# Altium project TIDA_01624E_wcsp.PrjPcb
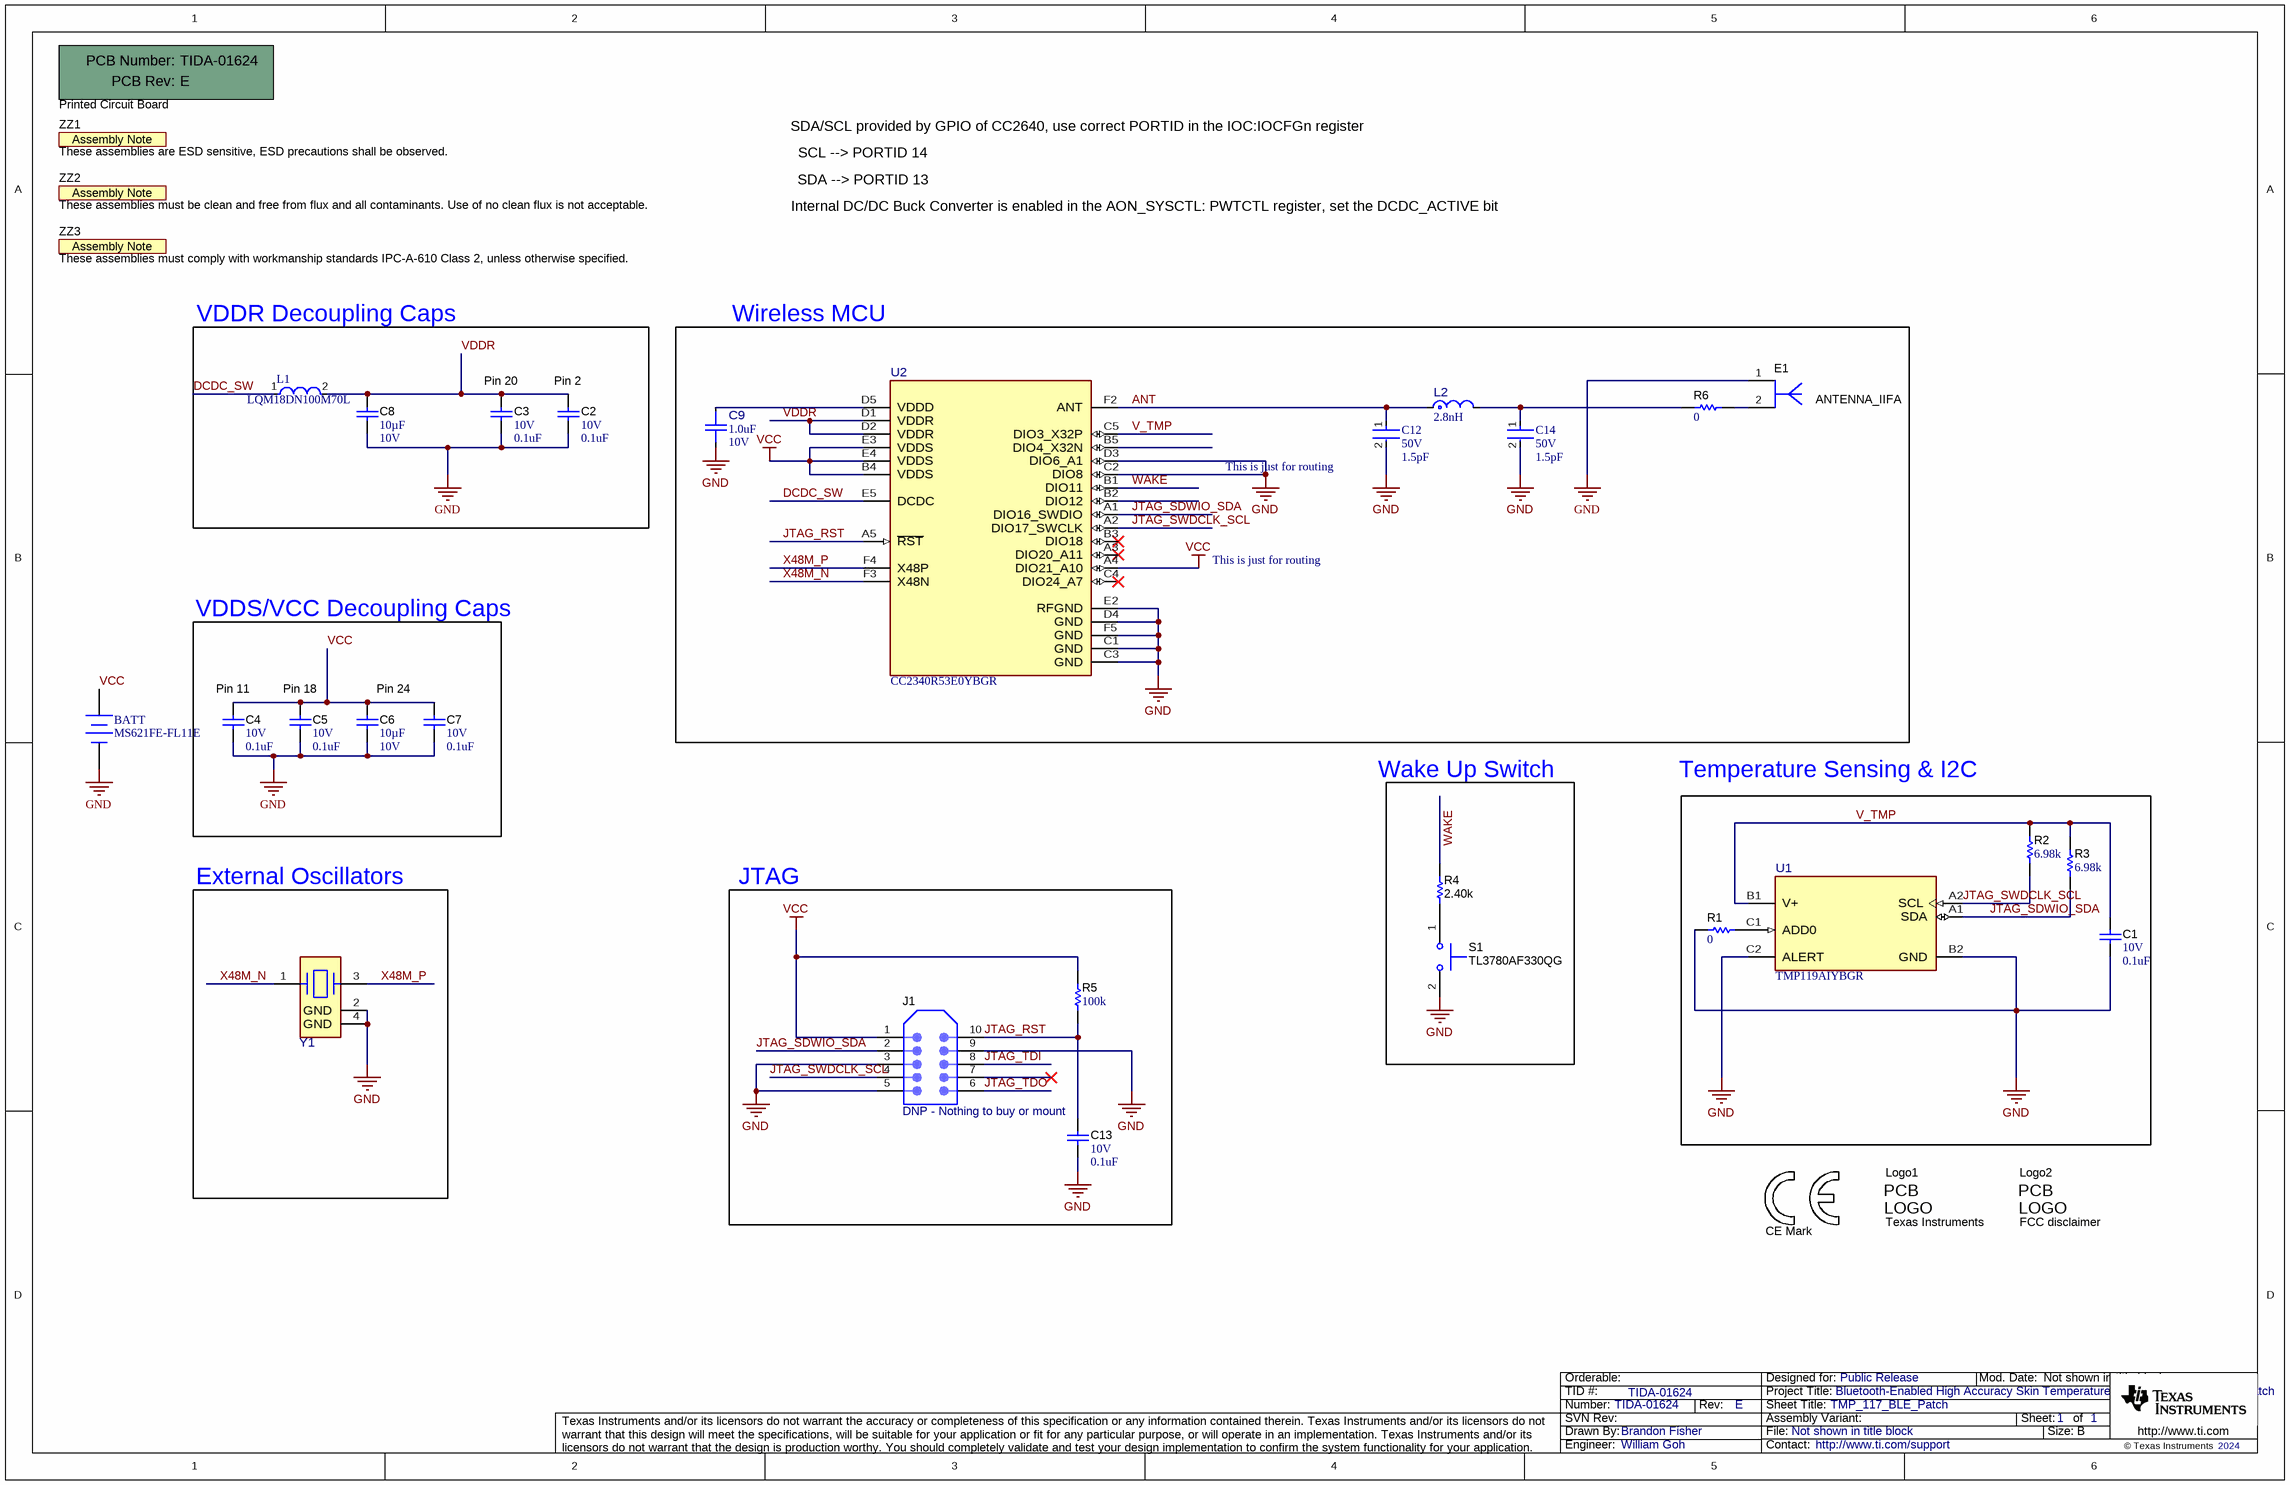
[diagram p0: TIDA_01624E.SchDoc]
TID: TIDA-01624; TechSupport: http://www.ti.com/support; SCH_Rev: E; PRJ_Title: Bluetooth-Enabled High Accuracy Skin Temperature Measurement Flex PCB Patch; PRJ_Number: TIDA-01624; PRJ_Engineer: William Goh; PRJ_Customer: Public Release; PCB_Rev: E; PCB_Layout: William Goh; CopyrightYear: 2024
1 sheet, 34 parts. Net scope: global (net labels, ports and power ports of the same name join across sheets).
Board file: TIDA_01624E.PcbDoc

## Sheet TIDA_01624E.SchDoc: TMP_117_BLE_Patch
size 431 x 279 mm; Date: Not shown in title block; ApprovedBy: Not shown in title block; CheckedBy: Not shown in title block; Author: Not shown in title block; CompanyName: Not shown in title block; DrawnBy: Brandon Fisher; Engineer: Not shown in title block; Organization: Not shown in title block; Address1: Not shown in title block; Address2: Not shown in title block; Address3: Not shown in title block; Address4: Not shown in title block; DocumentNumber: 1; Revision: Use project parameter SCH_Rev; SheetNumber: 1; SheetTotal: 1; PageSetup: Record=PageOptions¦CenterHorizontal=True¦CenterVertical=True¦PrintScale=1.00¦XCorrection=1.00¦YCorrection=1.00¦PrintKind=0¦BorderSize=5000000¦LeftOffset=0¦BottomOffset=0¦Orientation=2¦PaperLength=1000¦PaperWidth=1000¦Scale=100¦PaperSource=15¦PrintQuality=600¦MediaType=1¦DitherType=10¦PaperKind=Letter¦PrintScaleMode=1

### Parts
!PCB1  Printed Circuit Board  (mechanical)
BATT  MS621FE-FL11E  [SEIK-MS621FE-FL11E-2_V]
C1  VDC_V: 10V  ValueDisplayed: 0.1uF  [0201]  (hidden comment: GRM033C71A104KE14D)
C2  VDC_V: 10V  ValueDisplayed: 0.1uF  [0201]  (hidden comment: GRM033C71A104KE14D)
C3  VDC_V: 10V  ValueDisplayed: 0.1uF  [0201]  (hidden comment: GRM033C71A104KE14D)
C4  VDC_V: 10V  ValueDisplayed: 0.1uF  [0201]  (hidden comment: GRM033C71A104KE14D)
C5  VDC_V: 10V  ValueDisplayed: 0.1uF  [0201]  (hidden comment: GRM033C71A104KE14D)
C6  Cap_F: 10µF  VDC_V: 10V  [0603]  (hidden comment: GRM188Z71A106KA73D)
C7  VDC_V: 10V  ValueDisplayed: 0.1uF  [0201]  (hidden comment: GRM033C71A104KE14D)
C8  Cap_F: 10µF  VDC_V: 10V  [0603]  (hidden comment: GRM188Z71A106KA73D)
C9  ValueDisplayed: 1.0uF  VDC_V: 10V  [FP-GRM155Z71A105KE01D_0402-MFG]  (hidden comment: GRM155Z71A105KE01D)
C12  Voltage Rating: 50V  Capacitance: 1.5pF  [FP-GRM033-0_03-IPC_C]  (hidden comment: GRM0335C1H1R5BA01J)
C13  VDC_V: 10V  ValueDisplayed: 0.1uF  [0201]  (hidden comment: GRM033C71A104KE14D)
C14  Voltage Rating: 50V  Capacitance: 1.5pF  [FP-GRM033-0_03-IPC_C]  (hidden comment: GRM0335C1H1R5BA01J)
E1  ANTENNA_IIFA  [ANTENNA_IIFA]  (net tie)
J1  DNP - Nothing to buy or mount  [Tag_TC2050-NL]  (no BOM)
L1  LQM18DN100M70L  [FP-LQM18DN_70-IPC_B]
L2  value 2.8nH  [FP-LQP03TN2N8B02J_0201 (0603)-MFG]  (hidden comment: LQP03TN2N8B02J)
Logo1  Texas Instruments  [TI_Symbol_Overlay_Small]  (no BOM)
Logo2  FCC disclaimer  [FCC_disclaimer]  (no BOM)
Logo4  CE Mark  [CE_Mark_5mm]  (no BOM)
R1  ValueDisplayed: 0  [0402L]  (hidden comment: RC0402JR-070RL)
R2  ValueDisplayed: 6.98k  [0201]  (hidden comment: RC0201FR-7D6K98L)
R3  ValueDisplayed: 6.98k  [0201]  (hidden comment: RC0201FR-7D6K98L)
R4  ValueDisplayed: 2.40k  [0402]  (hidden comment: ERJ-2RKF2401X)
R5  ValueDisplayed: 100k  [0201]  (hidden comment: RC0201JR-7D100KL)
R6  ValueDisplayed: 0  [0201]  (hidden comment: CRCW02010000Z0ED)
S1  TL3780AF330QG  [SW_TL3780]
U1  TMP119AIYBGR  [YBG0006-C01-MFG]
U2  CC2340R53E0YBGR  [YBG0028-C01-MFG]
Y1  TZ3908AAAO43  [FP-TZ3908AAAO43_SMT4_2MM05_1MM65-MFG]  (value not drawn)
ZZ1  These assemblies are ESD sensitive, ESD precautions shall be observed.  [AssemblyNote]  (no BOM)
ZZ2  These assemblies must be clean and free from flux and all contaminants. Use of no clean flux is not acceptable.  [AssemblyNote]  (no BOM)
ZZ3  These assemblies must comply with workmanship standards IPC-A-610 Class 2, unless otherwise specified.  [AssemblyNote]  (no BOM)

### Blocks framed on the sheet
VDDR Decoupling Caps: C2 C3 C8 L1
Wireless MCU: C9 C12 C14 E1 L2 R6 U2
VDDS/VCC Decoupling Caps: C4-C7
Wake Up Switch: R4 S1
External Oscillators: Y1
JTAG: C13 J1 R5

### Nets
GND: BATT.2(-) C1.1 C2.1 C3.1 C4.1 C5.1 C6.1 C7.1 C8.1 C9.2 C12.2 C13.1 C14.2 E1.1 J1.3 J1.5 J1.9 R1.2 S1.2 U1.B2(GND) U1.C2(ALERT) U2.C1(GND) U2.C2(DIO8) U2.C3(GND) U2.D3(DIO6_A1) U2.D4(GND) U2.E2(RFGND) U2.F5(GND) Y1.2(GND) Y1.4(GND)
VCC: BATT.1(+) C4.2 C5.2 C6.2 C7.2 J1.1 R5.1 U2.A4(DIO21_A10) U2.B4(VDDS) U2.E3(VDDS) U2.E4(VDDS)
ANT: C12.1 L2.1 U2.F2(ANT)
DCDC_SW: L1.1 U2.E5(DCDC)
JTAG_RST: C13.2 J1.10 R5.2 U2.A5(~{RST})
JTAG_SDWIO_SDA: J1.2 R3.2 U1.A1(SDA) U2.A1(DIO16_SWDIO)
JTAG_SWDCLK_SCL: J1.4 R2.2 U1.A2(SCL) U2.A2(DIO17_SWCLK)
JTAG_TDI: J1.8
JTAG_TDO: J1.6
V_TMP: C1.2 R2.1 R3.1 U1.B1(V+) U2.C5(DIO3_X32P)
VDDR: C2.2 C3.2 C8.2 L1.2 U2.D1(VDDR) U2.D2(VDDR)
WAKE: R4.1 U2.B1(DIO11)
X48M_N: U2.F3(X48N) Y1.1(1_IN/OUT)
X48M_P: U2.F4(X48P) Y1.3(2_IN/OUT)
NetC9_1: C9.1 U2.D5(VDDD)
NetC14_1: C14.1 L2.2 R6.1
NetE1_2: E1.2 R6.2
NetR1_1: R1.1 U1.C1(ADD0)
NetR4_2: R4.2 S1.1

Not connected (* = marked no-connect by the designer): J1 7*; U2 A3(DIO20_A11)* B2(DIO12) B3(DIO18)* B5(DIO4_X32N) C4(DIO24_A7)*

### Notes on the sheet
- SCL --> PORTID 14
- SDA/SCL provided by GPIO of CC2640, use correct PORTID in the IOC:IOCFGn register
- SDA --> PORTID 13
- Internal DC/DC Buck Converter is enabled in the AON_SYSCTL: PWTCTL register, set the DCDC_ACTIVE bit
- (near C3) Pin 20
- (near C2) Pin 2
- (near C12) This is just for routing
- This is just for routing
- (near C4) Pin 11
- (near C5) Pin 18
- Pin 24
- Temperature Sensing & I2C

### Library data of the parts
!PCB1 = CMP-0003618-2: Manufacturer: Any; PartNumber: TIDA-01624
BATT = CMP-2000-05342-1: MS Lihium Rechargeable Battery, 3 V, -20 to 60 degC, Tray; Manufacturer: SeikoInstruments; Brand: SeikoInstrumentsMicroEnergy; Output Voltage: 3V; Capacity: 5.5mAh; Chemistry: Lithium; Battery Size: 621; Unit Weight: 0.008113oz
C1-C5 C7 C13 = CMP-0064969-1: CAP, CERM, 0.1 uF, 10 V,+/- 10%, X7S, 0201; Manufacturer: MuRata; TaMin_C: -55°C; Polarized: N; SizeAreaWB_mm2: 2.08; Value1: Unknown; U/M: EA; Value: 0.1uF; TaMax_C: 125°C; SizeZ_mm: 0.26; SizeX_mm: 0.6; SizeY_mm: 0.3; SizeArea_mm2: 0.18; Cap_F: 100nF; AEC Category: Q200
C6 C8 = CMP-0087107-2: Chip Multilayer Ceramic Capacitors for General Purpose; Manufacturer: Murata; TempCo: 15%; AEC Qualified: No; SizeZ_mm: 1mm; Tolerance_%: 10%
C9 = CMP-0092999-1: Chip Multilayer Ceramic Capacitors for General Purpose, 0402, 1.0uF, X7R, 15%, 10%, 10V; Manufacturer: Murata; Cap_F: 1µF; AEC Qualified: No; SizeZ_mm: 0.6mm; Value: 1µF
C12 C14 = CMP-06035-002174-1: Chip Multilayer Ceramic Capacitors for General Purpose, 0201, 1.5pF, C0G, 30ppm/°C, 0.1pF, 50V
E1 = CMP-0001736-1: PCB Antenna.  There is nothing to buy or mount.
J1 = CMP-0075101-1: Footprint for Tag-Connect TC2050 No-Legs cables; PartNumber: TC2050-IDC-NL-FP; Note: Footprint only, to mate with Tag-Connect TC2050 No-Legs cables; CT: False; CompType: Receptacle
L1 = CMP-06042-017052-1: Multilayer type Inductor for Power Lines 10uH ±20% @1MHz, 300mA, Max DCR 1.365Ω, SRF 32MHz
L2 = CMP-0001349-1: Film type RF Inductor 2.8nH ±0.1nH 500mA 0.2Ω 0201 (0603); Manufacturer: Murata; AEC Qualified: No; DCR_ohm: 0.2; SizeZ_mm: 0.33mm; Q Factor: 14; Self Resonant Frequency: 9.5GHz; Test Frequency: 500MHz
Logo1 = CMP-0074838-1: Texas Instrument Corporate Signature; SymbolCreator: a0412235; Lib Reference: TI_Logo
Logo2 = CMP-0074847-1: FCC_disclaimer
Logo4 = CMP-0074844-1: SymbolCreator: a0412235
R1 = CMP-0027004-2: RES, 0, 5%, 0.063 W, 0402; Manufacturer: Yageo America; Power_W: 63mW; TempCo: 200 ppm/C; Value_Code: 0000; U/M: EA; Value: 0; EIA_Code: E24; SizeX_mm: 1; SizeY_mm: 0.5; SizeZ_mm: 0.6; Value2: 0.063W; VDC_V: 50V; AEC Category: Q200
R2 R3 = CMP-0028058-1: RES, 6.98 k, 1%, 0.05 W, 0201; Manufacturer: Yageo America; Power_W: 50mW; TempCo: 200 ppm/C; Value_Code: 6k98; U/M: EA; Value: 6.98k; EIA_Code: E96; SizeX_mm: 0.6; SizeY_mm: 0.3; SizeZ_mm: 0.26; Value2: 0.05W; SizeArea_mm2: 0.18; AEC Qualified: N; VDC_V: 25V; AEC Category: Q200
R4 = CMP-0026685-1: RES, 2.40 k, 1%, 0.1 W, AEC-Q200 Grade 0, 0402; Manufacturer: Panasonic; Power_W: 100mW; TempCo: 100 ppm/C; Value_Code: 2k40; U/M: EA; Value: 2.40k; Res_ohm: 2.4k; SizeX_mm: 1; SizeY_mm: 0.5; SizeZ_mm: 0.6; Value2: 0.1W; CompType: Resistor; AEC Qualified: Y; AEC Grade: 0; AEC Category: Q200
R5 = CMP-0027184-1: RES, 100 k, 5%, 0.05 W, 0201; Manufacturer: Yageo America; Power_W: 50mW; TempCo: 200 ppm/C; U/M: EA; Value: 100k; EIA_Code: E24; SizeX_mm: 0.6; SizeY_mm: 0.3; SizeZ_mm: 0.26; Value2: 0.05W; SizeArea_mm2: 0.18; AEC Qualified: N; VDC_V: 25V; AEC Category: Q200
R6 = CMP-0027008-4: RES, 0, 5%, 0.05 W, 0201; Manufacturer: Vishay-Dale; Power_W: 50mW; TempCo: ppm/C; Value_Code: 0000; Value: 0; EIA_Code: E24; SizeX_mm: 0.6; SizeY_mm: 0.3; SizeZ_mm: 0.26; Value2: 0.05W; SizeArea_mm2: 0.18; AEC Qualified: N; AEC Category: Q200
S1 = CMP-0084104-1: Switch, SPST-NO, 0.05 A, 12 VDC, SMT; Manufacturer: E-Switch; CurrentRating_mA: 50A; SizeAreaWB_mm2: 13.5; PositionCount: 1; SizeZ_mm: 0.7; SizeX_mm: 3.5; SizeY_mm: 2; SwitchFunction: Off-Mom; SizeArea_mm2: 7; VDC_V: 12V
U1 = CMP-0049997-1: High-Accuracy, Low-Power, Digital Temperature Sensor With SMBus™- and I2C-Compatible Interface; Manufacturer: Texas Instruments; SizeZ_mm: 0.531mm; AEC Qualified: No; Interface: I2C,SMBus; Max Supply Voltage: 5.5V; Min Supply Voltage: 1.7V; Operating Supply Current: 135uA; Resolution: 16bits; Standoff Height: 0.16mm; TaMax_C: +150°C; TaMin_C: -55°C; TJmax_C: +155°C
U2 = CMP-0122602-1: Family SimpleLink™ Wireless MCU, DSBGA28; Manufacturer: Texas Instruments; SizeZ_mm: 0.5mm; AEC Qualified: No; Core Architecture: ARM Cortex-M0+; Data Bus Width: 32bits; Frequency_Fixed: 48MHz; Interface: I2C,SPI,UART; Max Supply Voltage: 3.8V; Memory Size: 512KBytes; Memory Type: FLASH; Min Supply Voltage: 1.71V; Number Of A/D Converters: 1; Number Of Adc Channels: 4; Number Of I/Os: 12; Number Of Pwm Channels: 7; Ram Size: 64KBytes; Standoff Height: 0.14mm; TaMax_C: +125°C; TaMin_C: -40°C
Y1 = CMP-0001392-1: Crystal Unit SMD 2.0x1.6 48.0MHz; Manufacturer: TAI-SAW Thechnology; Frequency Stability: 30ppm; Frequency_Fixed: 48MHz; SizeZ_mm: 0.5mm; AEC Qualified: No; Frequency Tolerance: 5ppm; Load Capacitance: 7pF; Esr: 30
ZZ1 = CMP-0077236-1
ZZ2 = CMP-0077237-1
ZZ3 = CMP-0077238-1

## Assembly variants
Default: not fitted J1 R7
